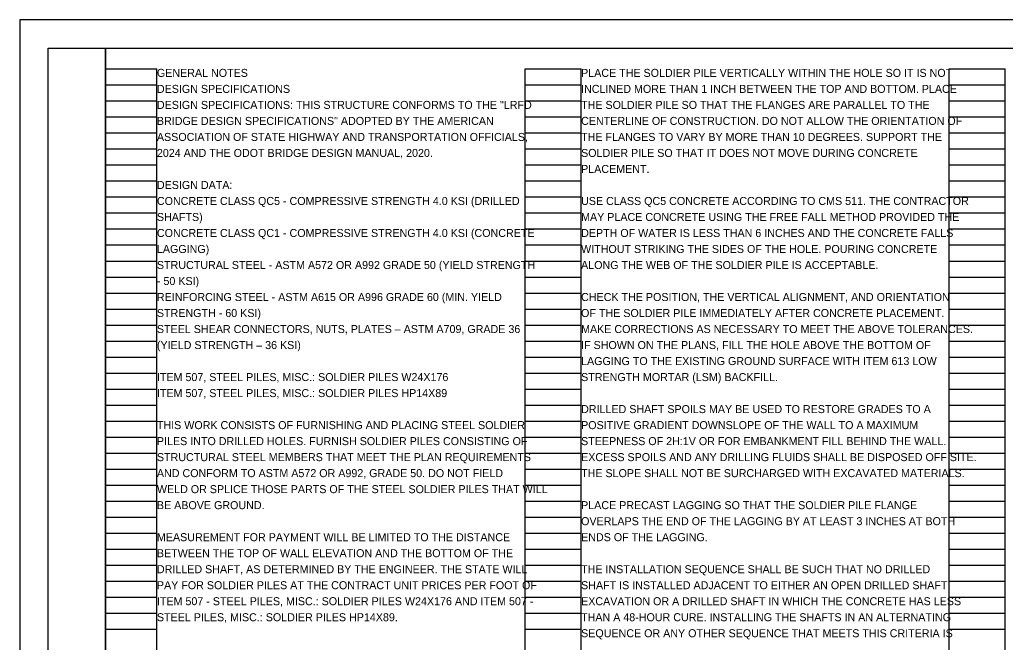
# Model space of a CAD drawing. Extents: x 0 to 34, y 0 to 22.
# Drawn here: x 0 to 17.24, y 11.11 to 22 of the extents above; entities that cross this region are included whole.
import ezdxf

# ---------------------------------------------------------------- set-up
doc = ezdxf.new("R2010")
doc.units = 0
for name, color, linetype in [('Default', 7, 'Continuous'), ('SH_Border', 7, 'Continuous'), ('SH_Cut_Line', 7, 'Continuous'), ('SH_Data', 7, 'Continuous')]:
    doc.layers.add(name, color=color, linetype=linetype)

msp = doc.modelspace()

# ---------------------------------------------------------------- linework, layer by layer
at = {"layer": 'SH_Border'}
for points in [[(0.5, 21.5), (1.5, 21.5), (1.5, 0.5), (0.5, 0.5)], [(1.5, 21.5), (33.5, 21.5), (33.5, 0.5), (1.5, 0.5)]]:
    msp.add_lwpolyline(points, close=True, dxfattribs=at)
at = {"layer": 'SH_Cut_Line'}
msp.add_lwpolyline([(0, 0), (34, 0), (34, 22), (0, 22)], close=True, dxfattribs=at)
at = {"layer": 'SH_Data'}
for p, q in [((1.5, 0.98), (1.5, 21.14)), ((1.5, 21.14), (2.4, 21.14)), ((2.4, 0.98), (2.4, 21.14)), ((8.84, 0.98), (8.84, 21.14)), ((8.84, 21.14), (9.82, 21.14)), ((9.82, 0.98), (9.82, 21.14)), ((16.26, 0.98), (16.26, 21.14)), ((16.26, 21.14), (17.24, 21.14)), ((17.24, 0.98), (17.24, 21.14)), ((1.5, 20.86), (2.4, 20.86)), ((8.84, 20.86), (9.82, 20.86)), ((16.26, 20.86), (17.24, 20.86)), ((1.5, 20.58), (2.4, 20.58)), ((8.84, 20.58), (9.82, 20.58)), ((16.26, 20.58), (17.24, 20.58)), ((1.5, 20.3), (2.4, 20.3)), ((8.84, 20.3), (9.82, 20.3)), ((16.26, 20.3), (17.24, 20.3)), ((1.5, 20.02), (2.4, 20.02)), ((8.84, 20.02), (9.82, 20.02)), ((16.26, 20.02), (17.24, 20.02)), ((1.5, 19.74), (2.4, 19.74)), ((8.84, 19.74), (9.82, 19.74)), ((16.26, 19.74), (17.24, 19.74)), ((1.5, 19.46), (2.4, 19.46)), ((8.84, 19.46), (9.82, 19.46)), ((16.26, 19.46), (17.24, 19.46)), ((1.5, 19.18), (2.4, 19.18)), ((8.84, 19.18), (9.82, 19.18)), ((16.26, 19.18), (17.24, 19.18)), ((1.5, 18.9), (2.4, 18.9)), ((8.84, 18.9), (9.82, 18.9)), ((16.26, 18.9), (17.24, 18.9)), ((1.5, 18.62), (2.4, 18.62)), ((8.84, 18.62), (9.82, 18.62)), ((16.26, 18.62), (17.24, 18.62)), ((1.5, 18.34), (2.4, 18.34)), ((8.84, 18.34), (9.82, 18.34)), ((16.26, 18.34), (17.24, 18.34)), ((1.5, 18.06), (2.4, 18.06)), ((8.84, 18.06), (9.82, 18.06)), ((16.26, 18.06), (17.24, 18.06)), ((1.5, 17.78), (2.4, 17.78)), ((8.84, 17.78), (9.82, 17.78)), ((16.26, 17.78), (17.24, 17.78)), ((1.5, 17.5), (2.4, 17.5)), ((8.84, 17.5), (9.82, 17.5)), ((16.26, 17.5), (17.24, 17.5)), ((1.5, 17.22), (2.4, 17.22)), ((8.84, 17.22), (9.82, 17.22)), ((16.26, 17.22), (17.24, 17.22)), ((1.5, 16.94), (2.4, 16.94)), ((8.84, 16.94), (9.82, 16.94)), ((16.26, 16.94), (17.24, 16.94)), ((1.5, 16.66), (2.4, 16.66)), ((8.84, 16.66), (9.82, 16.66)), ((16.26, 16.66), (17.24, 16.66)), ((1.5, 16.38), (2.4, 16.38)), ((8.84, 16.38), (9.82, 16.38)), ((16.26, 16.38), (17.24, 16.38)), ((1.5, 16.1), (2.4, 16.1)), ((8.84, 16.1), (9.82, 16.1)), ((16.26, 16.1), (17.24, 16.1)), ((1.5, 15.82), (2.4, 15.82)), ((8.84, 15.82), (9.82, 15.82)), ((16.26, 15.82), (17.24, 15.82)), ((1.5, 15.54), (2.4, 15.54)), ((8.84, 15.54), (9.82, 15.54)), ((16.26, 15.54), (17.24, 15.54)), ((1.5, 15.26), (2.4, 15.26)), ((8.84, 15.26), (9.82, 15.26)), ((16.26, 15.26), (17.24, 15.26)), ((1.5, 14.98), (2.4, 14.98)), ((8.84, 14.98), (9.82, 14.98)), ((16.26, 14.98), (17.24, 14.98)), ((1.5, 14.7), (2.4, 14.7)), ((8.84, 14.7), (9.82, 14.7)), ((16.26, 14.7), (17.24, 14.7)), ((1.5, 14.42), (2.4, 14.42)), ((8.84, 14.42), (9.82, 14.42)), ((16.26, 14.42), (17.24, 14.42)), ((1.5, 14.14), (2.4, 14.14)), ((8.84, 14.14), (9.82, 14.14)), ((16.26, 14.14), (17.24, 14.14)), ((1.5, 13.86), (2.4, 13.86)), ((8.84, 13.86), (9.82, 13.86)), ((16.26, 13.86), (17.24, 13.86)), ((1.5, 13.58), (2.4, 13.58)), ((8.84, 13.58), (9.82, 13.58)), ((16.26, 13.58), (17.24, 13.58)), ((1.5, 13.3), (2.4, 13.3)), ((8.84, 13.3), (9.82, 13.3)), ((16.26, 13.3), (17.24, 13.3)), ((1.5, 13.02), (2.4, 13.02)), ((8.84, 13.02), (9.82, 13.02)), ((16.26, 13.02), (17.24, 13.02)), ((1.5, 12.74), (2.4, 12.74)), ((8.84, 12.74), (9.82, 12.74)), ((16.26, 12.74), (17.24, 12.74)), ((1.5, 12.46), (2.4, 12.46)), ((8.84, 12.46), (9.82, 12.46)), ((16.26, 12.46), (17.24, 12.46)), ((1.5, 12.18), (2.4, 12.18)), ((8.84, 12.18), (9.82, 12.18)), ((16.26, 12.18), (17.24, 12.18)), ((1.5, 11.9), (2.4, 11.9)), ((8.84, 11.9), (9.82, 11.9)), ((16.26, 11.9), (17.24, 11.9)), ((1.5, 11.62), (2.4, 11.62)), ((8.84, 11.62), (9.82, 11.62)), ((16.26, 11.62), (17.24, 11.62)), ((1.5, 11.34), (2.4, 11.34)), ((8.84, 11.34), (9.82, 11.34)), ((16.26, 11.34), (17.24, 11.34))]:
    msp.add_line(p, q, dxfattribs=at)

# ---------------------------------------------------------------- texts
at = {"layer": 'Default'}
for s, p in [('GENERAL NOTES', (2.4, 21)), ('PLACE THE SOLDIER PILE VERTICALLY WITHIN THE HOLE SO IT IS NOT ', (9.82, 21)), ('DESIGN SPECIFICATIONS', (2.4, 20.72)), ('INCLINED MORE THAN 1 INCH BETWEEN THE TOP AND BOTTOM. PLACE ', (9.82, 20.72)), ('DESIGN SPECIFICATIONS: THIS STRUCTURE CONFORMS TO THE "LRFD ', (2.4, 20.44)), ('THE SOLDIER PILE SO THAT THE FLANGES ARE PARALLEL TO THE ', (9.82, 20.44)), ('BRIDGE DESIGN SPECIFICATIONS" ADOPTED BY THE AMERICAN ', (2.4, 20.16)), ('CENTERLINE OF CONSTRUCTION. DO NOT ALLOW THE ORIENTATION OF ', (9.82, 20.16)), ('ASSOCIATION OF STATE HIGHWAY AND TRANSPORTATION OFFICIALS, ', (2.4, 19.88)), ('THE FLANGES TO VARY BY MORE THAN 10 DEGREES. SUPPORT THE ', (9.82, 19.88)), ('2024 AND THE ODOT BRIDGE DESIGN MANUAL, 2020.', (2.4, 19.6)), ('SOLDIER PILE SO THAT IT DOES NOT MOVE DURING CONCRETE ', (9.82, 19.6)), ('PLACEMENT. ', (9.82, 19.32)), ('DESIGN DATA:', (2.4, 19.04)), ('CONCRETE CLASS QC5 - COMPRESSIVE STRENGTH 4.0 KSI (DRILLED ', (2.4, 18.76)), ('USE CLASS QC5 CONCRETE ACCORDING TO CMS 511. THE CONTRACTOR ', (9.82, 18.76)), ('SHAFTS)', (2.4, 18.48)), ('MAY PLACE CONCRETE USING THE FREE FALL METHOD PROVIDED THE ', (9.82, 18.48)), ('CONCRETE CLASS QC1 - COMPRESSIVE STRENGTH 4.0 KSI (CONCRETE ', (2.4, 18.2)), ('DEPTH OF WATER IS LESS THAN 6 INCHES AND THE CONCRETE FALLS ', (9.82, 18.2)), ('LAGGING)', (2.4, 17.92)), ('WITHOUT STRIKING THE SIDES OF THE HOLE. POURING CONCRETE ', (9.82, 17.92)), ('STRUCTURAL STEEL - ASTM A572 OR A992 GRADE 50 (YIELD STRENGTH ', (2.4, 17.64)), ('ALONG THE WEB OF THE SOLDIER PILE IS ACCEPTABLE.', (9.82, 17.64)), ('- 50 KSI)', (2.4, 17.36)), ('REINFORCING STEEL - ASTM A615 OR A996 GRADE 60 (MIN. YIELD ', (2.4, 17.08)), ('CHECK THE POSITION, THE VERTICAL ALIGNMENT, AND ORIENTATION ', (9.82, 17.08)), ('STRENGTH - 60 KSI)', (2.4, 16.8)), ('OF THE SOLDIER PILE IMMEDIATELY AFTER CONCRETE PLACEMENT. ', (9.82, 16.8)), ('STEEL SHEAR CONNECTORS, NUTS, PLATES – ASTM A709, GRADE 36 ', (2.4, 16.52)), ('MAKE CORRECTIONS AS NECESSARY TO MEET THE ABOVE TOLERANCES. ', (9.82, 16.52)), ('(YIELD STRENGTH – 36 KSI) ', (2.4, 16.24)), ('IF SHOWN ON THE PLANS, FILL THE HOLE ABOVE THE BOTTOM OF ', (9.82, 16.24)), ('LAGGING TO THE EXISTING GROUND SURFACE WITH ITEM 613 LOW ', (9.82, 15.96)), ('ITEM 507, STEEL PILES, MISC.: SOLDIER PILES W24X176', (2.4, 15.68)), ('STRENGTH MORTAR (LSM) BACKFILL.', (9.82, 15.68)), ('ITEM 507, STEEL PILES, MISC.: SOLDIER PILES HP14X89', (2.4, 15.4)), ('DRILLED SHAFT SPOILS MAY BE USED TO RESTORE GRADES TO A ', (9.82, 15.12)), ('THIS WORK CONSISTS OF FURNISHING AND PLACING STEEL SOLDIER ', (2.4, 14.84)), ('POSITIVE GRADIENT DOWNSLOPE OF THE WALL TO A MAXIMUM ', (9.82, 14.84)), ('PILES INTO DRILLED HOLES. FURNISH SOLDIER PILES CONSISTING OF ', (2.4, 14.56)), ('STEEPNESS OF 2H:1V OR FOR EMBANKMENT FILL BEHIND THE WALL. ', (9.82, 14.56)), ('STRUCTURAL STEEL MEMBERS THAT MEET THE PLAN REQUIREMENTS ', (2.4, 14.28)), ('EXCESS SPOILS AND ANY DRILLING FLUIDS SHALL BE DISPOSED OFF SITE. ', (9.82, 14.28)), ('AND CONFORM TO ASTM A572 OR A992, GRADE 50. DO NOT FIELD ', (2.4, 14)), ('THE SLOPE SHALL NOT BE SURCHARGED WITH EXCAVATED MATERIALS.', (9.82, 14)), ('WELD OR SPLICE THOSE PARTS OF THE STEEL SOLDIER PILES THAT WILL ', (2.4, 13.72)), ('BE ABOVE GROUND. ', (2.4, 13.44)), ('PLACE PRECAST LAGGING SO THAT THE SOLDIER PILE FLANGE ', (9.82, 13.44)), ('OVERLAPS THE END OF THE LAGGING BY AT LEAST 3 INCHES AT BOTH ', (9.82, 13.16)), ('MEASUREMENT FOR PAYMENT WILL BE LIMITED TO THE DISTANCE ', (2.4, 12.88)), ('ENDS OF THE LAGGING. ', (9.82, 12.88)), ('BETWEEN THE TOP OF WALL ELEVATION AND THE BOTTOM OF THE ', (2.4, 12.6)), ('DRILLED SHAFT, AS DETERMINED BY THE ENGINEER. THE STATE WILL ', (2.4, 12.32)), ('THE INSTALLATION SEQUENCE SHALL BE SUCH THAT NO DRILLED ', (9.82, 12.32)), ('PAY FOR SOLDIER PILES AT THE CONTRACT UNIT PRICES PER FOOT OF ', (2.4, 12.04)), ('SHAFT IS INSTALLED ADJACENT TO EITHER AN OPEN DRILLED SHAFT ', (9.82, 12.04)), ('ITEM 507 - STEEL PILES, MISC.: SOLDIER PILES W24X176 AND ITEM 507 - ', (2.4, 11.76)), ('EXCAVATION OR A DRILLED SHAFT IN WHICH THE CONCRETE HAS LESS ', (9.82, 11.76)), ('STEEL PILES, MISC.: SOLDIER PILES HP14X89.', (2.4, 11.48)), ('THAN A 48-HOUR CURE. INSTALLING THE SHAFTS IN AN ALTERNATING ', (9.82, 11.48)), ('SEQUENCE OR ANY OTHER SEQUENCE THAT MEETS THIS CRITERIA IS ', (9.82, 11.2))]:
    msp.add_text(s, height=0.14, dxfattribs=at).set_placement(p)

doc.saveas('drawing.dxf')
